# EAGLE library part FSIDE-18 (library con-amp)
AMP connector
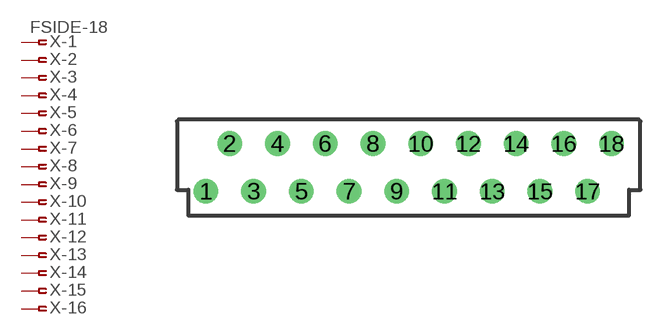
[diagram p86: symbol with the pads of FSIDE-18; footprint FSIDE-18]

Designator prefix X; gates -1=PIN-FV -2=PIN-F -3=PIN-F -4=PIN-F -5=PIN-F -6=PIN-F -7=PIN-F -8=PIN-F -9=PIN-F -10=PIN-F -11=PIN-F -12=PIN-F -13=PIN-F -14=PIN-F -15=PIN-F -16=PIN-F -17=PIN-F -18=PIN-F

## FSIDE-18 (OC_FARNELL: unknown; OC_NEWARK: unknown)  [FSIDE-18]
1  -1:1  pas
2  -2:1  pas
3  -3:1  pas
4  -4:1  pas
5  -5:1  pas
6  -6:1  pas
7  -7:1  pas
8  -8:1  pas
9  -9:1  pas
10  -10:1  pas
11  -11:1  pas
12  -12:1  pas
13  -13:1  pas
14  -14:1  pas
15  -15:1  pas
16  -16:1  pas
17  -17:1  pas
18  -18:1  pas

## Footprint FSIDE-18 (pad centres in mm)
AMP connector
drill 0.813 round: 1 -10.795,-1.27; 2 -9.525,1.27; 3 -8.255,-1.27; 4 -6.985,1.27; 5 -5.715,-1.27; 6 -4.445,1.27; 7 -3.175,-1.27; 8 -1.905,1.27; 9 -0.635,-1.27; 10 0.635,1.27; 11 1.905,-1.27; 12 3.175,1.27; 13 4.445,-1.27; 14 5.715,1.27; 15 6.985,-1.27; 16 8.255,1.27; 17 9.525,-1.27; 18 10.795,1.27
